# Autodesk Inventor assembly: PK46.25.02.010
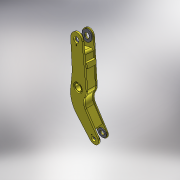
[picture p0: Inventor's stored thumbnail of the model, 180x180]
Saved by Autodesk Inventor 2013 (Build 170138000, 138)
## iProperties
Created: 2005-04
Part Number: PK46.25.02.010
Document SubType Name: Assembly
Designer: salex
Manufacturer: Standard
Standards Organization: Custom
Author: salex
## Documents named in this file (8)
- C:\Product Design Suite 2013 Test Drive\Dynamic Simulation\Workspace\Assy, Chassis, Front\PK46.25.02.010.iam
- C:\Product Design Suite 2013 Test Drive\Dynamic Simulation\Workspace\Assy, Chassis, Front\PK46.25.02.001.ipt
- C:\Product Design Suite 2013 Test Drive\Dynamic Simulation\Workspace\Assy, Chassis, Front\PK46.25.02.002.ipt
- C:\Product Design Suite 2013 Test Drive\Dynamic Simulation\Workspace\Assy, Chassis, Front\PK46.25.02.003.ipt
- C:\Product Design Suite 2013 Test Drive\Dynamic Simulation\Workspace\Assy, Chassis, Front\PK46.25.02.004.ipt
- C:\Product Design Suite 2013 Test Drive\Dynamic Simulation\Workspace\Assy, Chassis, Front\PK46.25.02.005.ipt
- C:\Product Design Suite 2013 Test Drive\Dynamic Simulation\Workspace\Assy, Chassis, Front\PK46.25.02.006.ipt
- C:\Product Design Suite 2013 Test Drive\Dynamic Simulation\Workspace\Assy, Chassis, Front\PK46.21.01.089.ipt
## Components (10 placed, 7 different names)
1. PK46.25.02.001:1 — Вставка:1, Совмещение:1, Совмещение:2, Вставка:3, Вставка:5, Совмещение:3, Совмещение:4, Заподлицо:1, Mate:10, Mate:11
2. PK46.25.02.002:1 — Вставка:2, Совмещение:1, Совмещение:2, Вставка:4, Вставка:6, Совмещение:7
3. PK46.25.02.003:1 — Вставка:4
4. PK46.25.02.003:2 — Вставка:3, Совмещение:8
5. PK46.25.02.003:3 — Вставка:5
6. PK46.25.02.003:4 — Вставка:6
7. PK46.25.02.004:1 — Вставка:1, Вставка:2
8. PK46.25.02.005:1 — Совмещение:3, Совмещение:5, Совмещение:6, Совмещение:7, Заподлицо:1
9. PK46.25.02.006:1 — Совмещение:4, Совмещение:5, Совмещение:6, Совмещение:8, Mate:9
10. PK46.21.01.089:1 — Mate:9, Mate:10, Mate:11
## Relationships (18: Mate 11, Insert 6, Flush 1)
- Вставка:1 [Insert]: PK46.25.02.001:1 ↔ PK46.25.02.004:1
- Вставка:2 [Insert]: PK46.25.02.002:1 ↔ PK46.25.02.004:1
- Совмещение:1 [Mate]: PK46.25.02.001:1 ↔ PK46.25.02.002:1
- Совмещение:2 [Mate]: PK46.25.02.001:1 ↔ PK46.25.02.002:1
- Вставка:3 [Insert]: PK46.25.02.001:1 ↔ PK46.25.02.003:2
- Вставка:4 [Insert]: PK46.25.02.002:1 ↔ PK46.25.02.003:1
- Вставка:5 [Insert]: PK46.25.02.001:1 ↔ PK46.25.02.003:3
- Вставка:6 [Insert]: PK46.25.02.002:1 ↔ PK46.25.02.003:4
- Совмещение:3 [Mate]: PK46.25.02.001:1 ↔ PK46.25.02.005:1
- Совмещение:4 [Mate]: PK46.25.02.001:1 ↔ PK46.25.02.006:1
- Совмещение:5 [Mate]: PK46.25.02.005:1 ↔ PK46.25.02.006:1
- Совмещение:6 [Mate]: PK46.25.02.005:1 ↔ PK46.25.02.006:1
- Совмещение:7 [Mate]: PK46.25.02.002:1 ↔ PK46.25.02.005:1
- Заподлицо:1 [Flush]: PK46.25.02.001:1 ↔ PK46.25.02.005:1
- Совмещение:8 [Mate]: PK46.25.02.003:2 ↔ PK46.25.02.006:1
- Mate:9: PK46.25.02.006:1 ↔ PK46.21.01.089:1
- Mate:10: PK46.25.02.001:1 ↔ PK46.21.01.089:1
- Mate:11: PK46.25.02.001:1 ↔ PK46.21.01.089:1
